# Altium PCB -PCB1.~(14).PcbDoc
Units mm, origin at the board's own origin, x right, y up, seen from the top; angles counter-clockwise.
Board outline 80 x 60 mm, 2 copper layers (Top Layer, Bottom Layer); 29 components, 21 nets, 66 pads, 0 vias.
Unrouted connection lines stored in the file: 45.
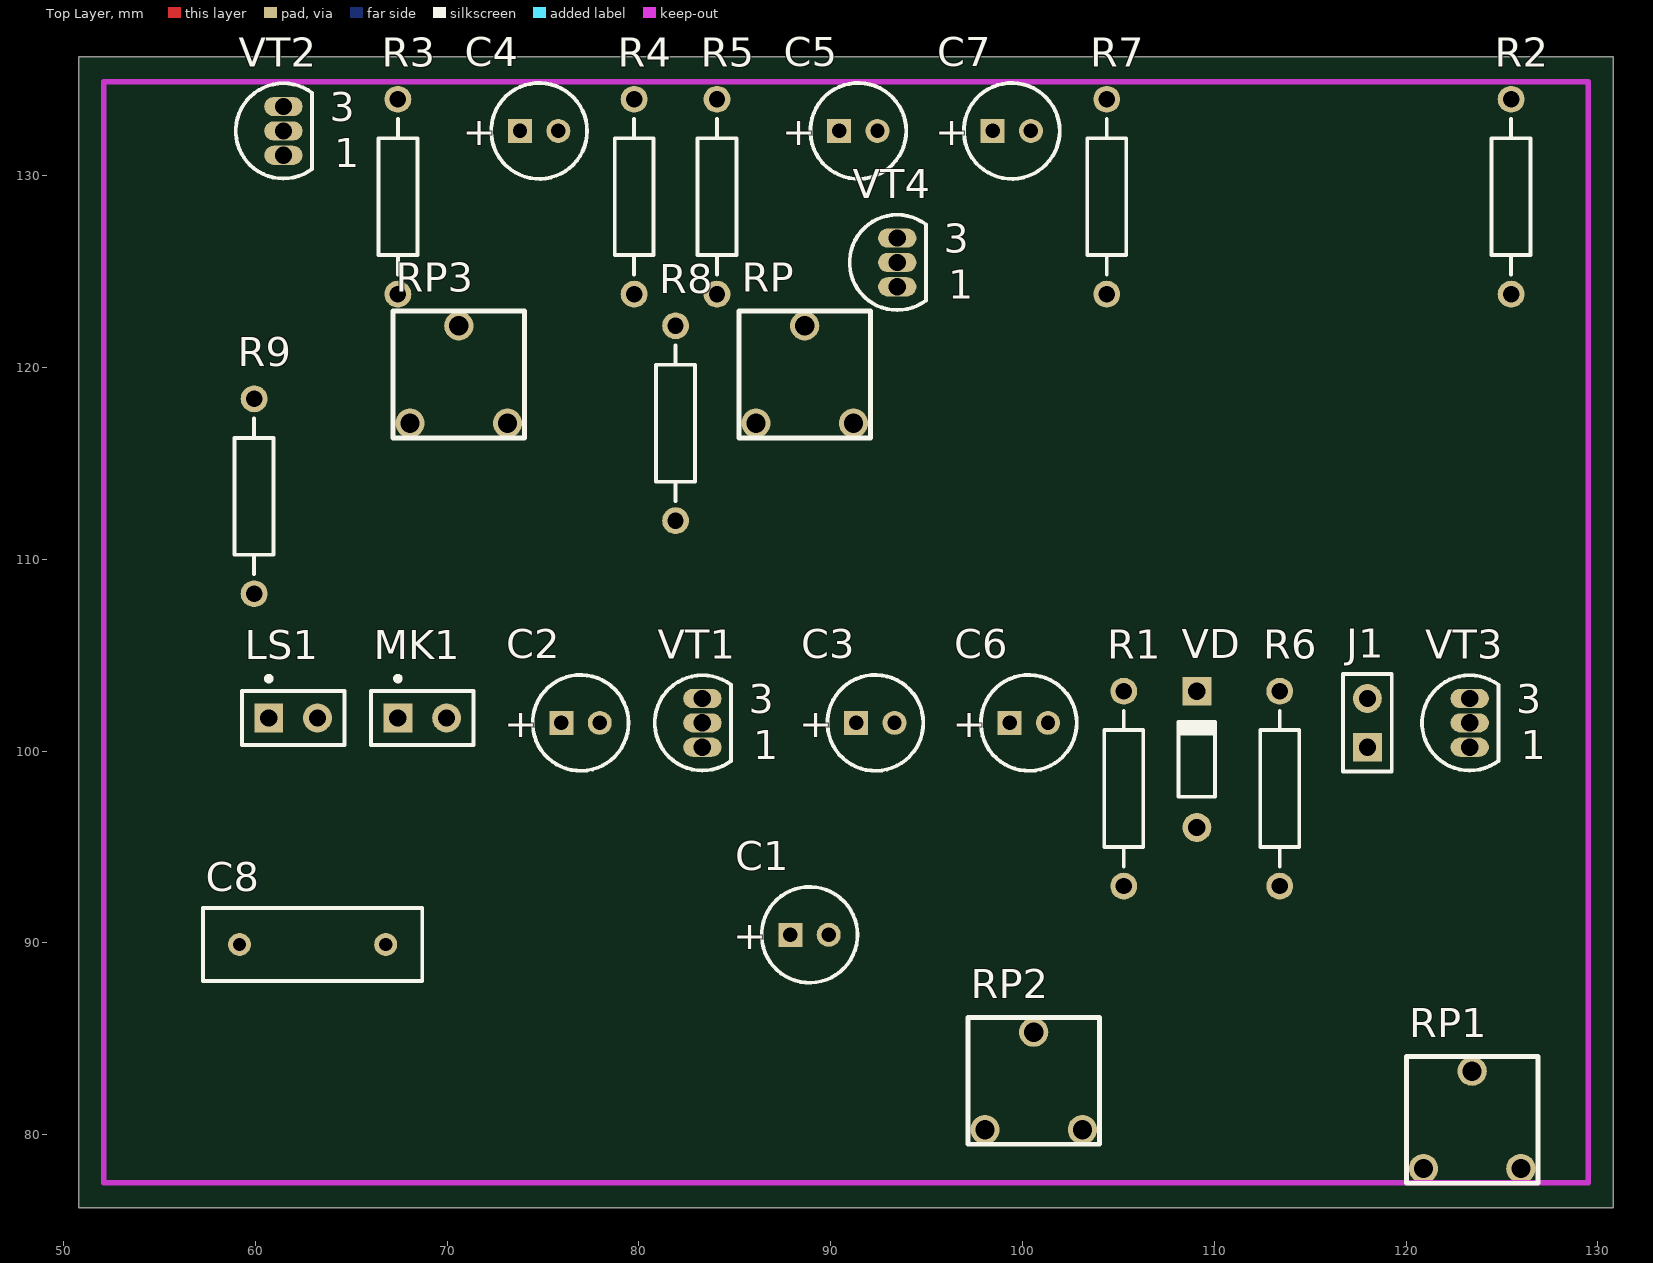
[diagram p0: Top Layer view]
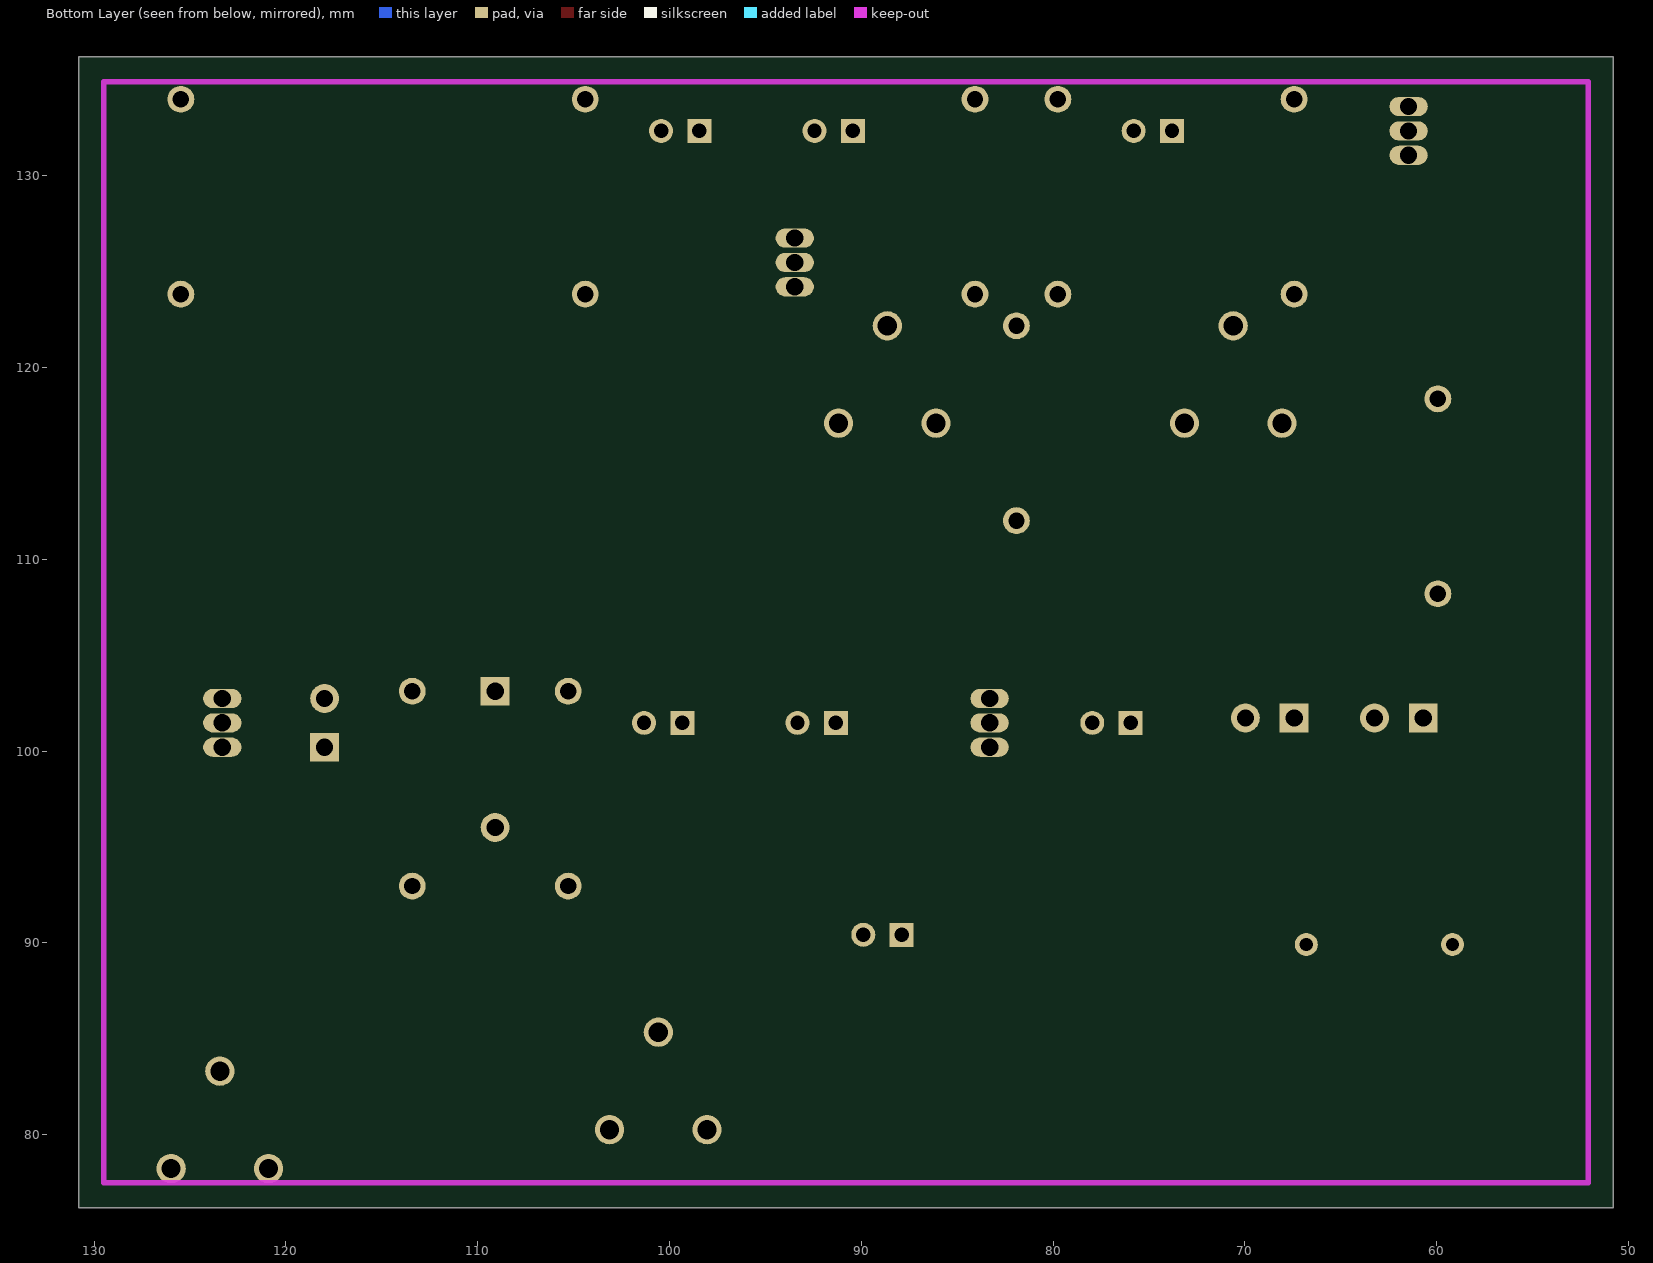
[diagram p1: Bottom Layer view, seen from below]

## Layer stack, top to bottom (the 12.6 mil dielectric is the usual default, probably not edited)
Top Layer: signal copper 0.0356
Dielectric: dielectric 0.32, FR-4, Dk 4.8
Bottom Layer: signal copper 0.0356

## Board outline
50.8,76.2 130.8,76.2 130.8,136.2 50.8,136.2

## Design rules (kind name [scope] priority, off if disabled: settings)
Clearance [All] p1: gap=0.33
ComponentClearance [All] p1: gap=0.254 collisioncheckmode=0
PolygonConnect [All] p1: connectstyle=Relief reliefconductorwidth=0.254 reliefentries=4 polygonreliefangle="90 Angle"
RoutingVias [All] p1: holewidth=0.813 width=2 viastyle="Through Hole" minholewidth=0.711 minwidth=1.27 maxholewidth=0.711 maxwidth=1.27
SolderMaskExpansion [All] p1: expansion=0.102
TestPointUsage [All] p1: valid=0 allowmultiple=FALSE
Testpoint [All] p1: side=15 testpointundercomponent=TRUE minsize=1.016 maxsize=2.54 preferedsize=1.524 minholesize=0 maxholesize=1.016 preferedholesize=0.813 testpointgrid=0.025 style=1023 order=-539222988
Width [All] p1: maxlimit=0.305 minlimit=0.305 preferedwidth=0.305
17 further rules are at their usual default settings.

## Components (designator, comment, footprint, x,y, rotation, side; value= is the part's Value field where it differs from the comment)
C1 "Cap Pol1" CAPPR2-5x6.8 88.9,90.424 r0 top
C2 "Cap Pol1" CAPPR2-5x6.8 76.962,101.473 r0 top
C3 "Cap Pol1" CAPPR2-5x6.8 92.329,101.473 r0 top
C4 "Cap Pol1" CAPPR2-5x6.8 74.803,132.334 r0 top
C5 "Cap Pol1" CAPPR2-5x6.8 91.44,132.334 r0 top
C6 "Cap Pol1" CAPPR2-5x6.8 100.33,101.473 r0 top
C7 "Cap Pol1" CAPPR2-5x6.8 99.441,132.334 r0 top
C8 "Cap" RAD-0.3 62.992,89.916 r0 top
J1 "MHDR1X2" HDR1X2 117.983,100.203 r90 top
LS1 "Speaker" PIN2 60.706,101.727 r0 top
MK1 "Mic" PIN2 67.437,101.727 r0 top
R1 "Res2" AXIAL-0.4 105.283,98.044 r90 top
R2 "Res2" AXIAL-0.4 125.476,128.905 r90 top
R3 "Res2" AXIAL-0.4 67.437,128.905 r90 top
R4 "Res2" AXIAL-0.4 79.756,128.905 r90 top
R5 "Res2" AXIAL-0.4 84.074,128.905 r90 top
R6 "Res2" AXIAL-0.4 113.411,98.044 r90 top
R7 "47" AXIAL-0.4 104.394,128.905 r90 top
R8 "Res2" AXIAL-0.4 81.915,117.094 r90 top
R9 "Res2" AXIAL-0.4 59.944,113.284 r90 top
RP "RPot" RM065 88.646,119.634 r0 top
RP1 "RPot" RM065 123.444,80.772 r0 top
RP2 "RPot" RM065 100.584,82.804 r0 top
RP3 "100" RM065 70.612,119.634 r0 top
VD "4148" DIO7.1-3.9x1.9 109.093,99.568 r90 top
VT1 "9014" BCY-W3/E4 83.312,101.473 r0 top
VT2 "9015" BCY-W3/E4 61.468,132.334 r0 top
VT3 "8050" BCY-W3/E4 123.317,101.473 r0 top
VT4 "8550" BCY-W3/E4 93.472,125.476 r0 top

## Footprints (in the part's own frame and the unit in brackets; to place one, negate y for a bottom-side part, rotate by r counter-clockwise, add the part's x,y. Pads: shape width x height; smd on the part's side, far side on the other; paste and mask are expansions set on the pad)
AXIAL-0.4 [mm] "Resistor; 2 Leads"
  round 1.4 hole 0.85: 1(-5.08,0) 2(5.08,0)
  silkscreen extent -4.06,-1.02 4.06,1.02
BCY-W3/E4 [mm] "TO, Flat Index; 3 In-Line, Axial Leads; Body Dia. 4.7mm"
  oval 2x1 hole 0.9: 1(0,-1.27) 2(0,0) 3(0,1.27)
  silkscreen extent -2.48,-2.48 1.5,2.48
CAPPR2-5x6.8 [mm] "Capacitor, Electrolytic, Radial; Body 5 x 6.8 mm (Dia.xH typ); Pin Spacing 2 mm (typ)"
  rect 1.25x1.25 hole 0.75: 1(-1,0)
  round 1.25 hole 0.75: 2(1,0)
  silkscreen extent -2.5,-2.5 2.5,2.5
DIO7.1-3.9x1.9 [mm] "Diode, Axial; Body 3.8 x 1.9 mm (LxDia. max), Lead Dia. 0.53 mm (max)"
  round 1.5 hole 0.9: 1(-3.55,0)
  rect 1.5x1.5 hole 0.9: 2(3.55,0)
  silkscreen extent -1.95,-0.95 2.05,0.95
HDR1X2 [mm] "Connector; Header; 2 Position"
  rect 1.5x1.5 hole 0.9: 1(0,0)
  round 1.5 hole 0.9: 2(2.54,0)
  silkscreen extent -1.27,-1.27 3.81,1.27
PIN2 [mm] "Photosensitive Diode; 2 Leads"
  rect 1.5x1.5 hole 0.9: 1(0,0)
  round 1.5 hole 0.9: 2(2.54,0)
  silkscreen extent -1.4,-1.4 3.94,2.17
RAD-0.3 [mm] "Capacitor; 2 Leads"
  round 1.2 hole 0.7: 1(-3.81,0) 2(3.81,0)
  silkscreen extent -5.71,-1.91 5.71,1.91
RM065 [mil]
  round 60 hole 39.37: 1(100,-100) 2(0,100) 3(-100,-100)
  silkscreen extent -135,-130 135,130

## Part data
C1 C2 C3 C4 C5 C6 C7: "Polarized Capacitor (Radial)"
C8: "Capacitor"
J1: library part "Header 2", "Header, 2-Pin"
LS1: "Loudspeaker"
MK1: library part Mic2, "Microphone"
R1 R2 R3 R4 R5 R6 R8 R9: "Resistor"
R7: library part Res2, "Resistor"
RP RP1 RP2: "Potentiometer"
RP3: library part RPot, "Potentiometer"
VD: library part "Diode 1N4148", "High Conductance Fast Diode"
VT1: library part 2N3904, "NPN General Purpose Amplifier"
VT2 VT3 VT4: library part 2N3906, "PNP General Purpose Amplifier"

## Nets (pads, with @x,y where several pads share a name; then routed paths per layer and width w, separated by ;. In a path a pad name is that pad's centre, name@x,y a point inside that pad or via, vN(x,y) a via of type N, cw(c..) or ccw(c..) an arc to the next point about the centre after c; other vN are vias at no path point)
GND: C1.2 C7.2 C8.1 J1.2 LS1.2 MK1.1 RP.2 VT1.1 VT4.3
NetC1_1: C1.1 R1.1 R2.2
NetC2_1: C2.1 MK1.2 R1.2
NetC2_2: C2.2 RP.3
NetC3_1: C3.1 RP.1
NetC3_2: C3.2 C8.2 R3.1 VT1.2
NetC4_1: C4.1 R3.2
NetC4_2: C4.2 VT2.2
NetC5_2: C5.2 R7.1 VT2.1
NetC6_1: C6.1 R6.1
NetC6_2: C6.2 LS1.1 R9.1
NetR4_1: R4.1 VT1.3
NetR4_2: R4.2 RP1.2
NetR5_1: R5.1 RP2.2
NetR5_2: R5.2 R6.2
NetR8_1: R8.1 RP3.1
NetR8_2: R8.2 R9.2 VT4.2
NetRP3_2: RP3.2 RP3.3 VD.2
NetVD_1: VD.1 VT2.3 VT3.2
NetVT3_3: VT3.3 VT4.1
VCC: C5.1 C7.1 J1.1 R2.1 R7.2 RP1.1 RP1.3 RP2.1 RP2.3 VT3.1

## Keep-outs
Keep-Out Layer:
  lines w0.3: 52.1,77.5 129.5,77.5 129.5,134.9 52.1,134.9 52.1,77.5

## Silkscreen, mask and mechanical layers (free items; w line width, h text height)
Drill Drawing:
  text ".LEGEND" at 135.88,81.28 h1.52
  text "Drill Drawing." at 135.88,78.74 h1.52

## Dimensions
52.1,77.5 to 129.5,77.5 on Mechanical 1
52.1,77.5 to 52.1,134.9 on Mechanical 1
